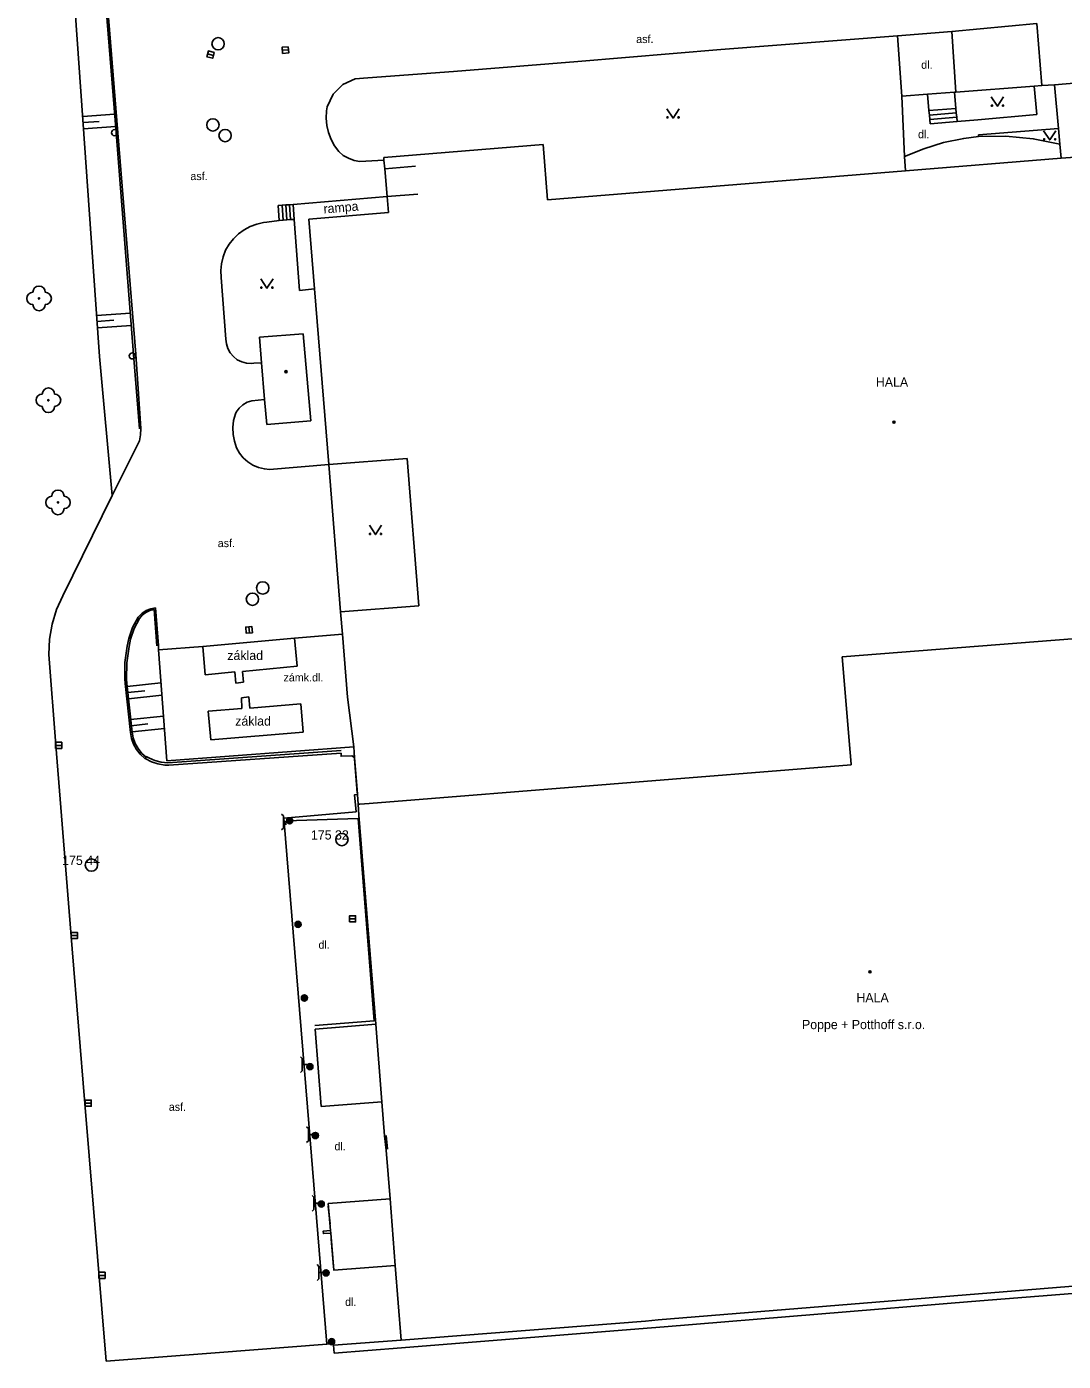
# Model space of a CAD drawing. Extents: x -541281 to -539153, y -1183881 to -1182141.
# Drawn here: x -539600.4 to -539516.2, y -1183333.1 to -1183224.7 of the extents above; entities that cross this region are included whole.
import ezdxf

# ---------------------------------------------------------------- set-up
doc = ezdxf.new("R2010")
doc.units = 0
for name, color, linetype in [('Vrstva 10', 7, 'Continuous'), ('Vrstva 11', 7, 'Continuous'), ('Vrstva 14', 7, 'Continuous'), ('Vrstva 15', 7, 'Continuous'), ('Vrstva 22', 7, 'Continuous'), ('Vrstva 25', 7, 'Continuous'), ('Vrstva 27', 7, 'Continuous'), ('Vrstva 28', 7, 'Continuous'), ('Vrstva 36', 7, 'Continuous'), ('Vrstva 39', 7, 'Continuous'), ('Vrstva 4', 7, 'Continuous'), ('Vrstva 40', 7, 'Continuous'), ('Vrstva 41', 7, 'Continuous'), ('Vrstva 5', 7, 'Continuous'), ('Vrstva 6', 7, 'Continuous')]:
    doc.layers.add(name, color=color, linetype=linetype)

msp = doc.modelspace()

# ---------------------------------------------------------------- linework, layer by layer
at = {"layer": 'Vrstva 10'}
for p, q in [((-539593, -1183233.35), (-539594.42, -1183215.51)), ((-539529.69, -1183225.47), (-539525.28, -1183225.11)), ((-539525.28, -1183225.11), (-539518.39, -1183224.47)), ((-539525.28, -1183225.11), (-539524.95, -1183230.04)), ((-539518.39, -1183224.47), (-539517.97, -1183229.5)), ((-539544.03, -1183226.57), (-539529.69, -1183225.47)), ((-539555.66, -1183227.54), (-539544.03, -1183226.57)), ((-539572.71, -1183228.87), (-539565.75, -1183228.37)), ((-539565.75, -1183228.37), (-539555.66, -1183227.54)), ((-539524.95, -1183230.04), (-539518.6, -1183229.55)), ((-539516.96, -1183229.43), (-539507.39, -1183228.66)), ((-539591.55, -1183251.33), (-539593, -1183233.35)), ((-539571.39, -1183235.55), (-539573.35, -1183235.67)), ((-539578.77, -1183239.16), (-539571.13, -1183238.5)), ((-539580.89, -1183240.6), (-539579.9, -1183240.46)), ((-539578.68, -1183240.37), (-539578.26, -1183246.15)), ((-539584.23, -1183250.09), (-539584.62, -1183245.1)), ((-539578.26, -1183246.15), (-539577.03, -1183246)), ((-539591.12, -1183257.35), (-539591.55, -1183251.33)), ((-539581.95, -1183252.06), (-539581.33, -1183252.01)), ((-539582.13, -1183255.1), (-539581.08, -1183255.01)), ((-539575.88, -1183260.29), (-539580.69, -1183260.68)), ((-539574.91, -1183272.25), (-539575.88, -1183260.29)), ((-539574.77, -1183274.06), (-539578.65, -1183274.38)), ((-539586.11, -1183275.06), (-539589.7, -1183275.32)), ((-539586.11, -1183275.06), (-539578.65, -1183274.38)), ((-539586.11, -1183275.06), (-539585.91, -1183277.35)), ((-539578.44, -1183276.67), (-539578.65, -1183274.38)), ((-539598.6, -1183275.72), (-539598.04, -1183283.07)), ((-539585.91, -1183277.35), (-539583.49, -1183277.13)), ((-539583.49, -1183277.13), (-539583.41, -1183278.03)), ((-539582.89, -1183277.08), (-539578.44, -1183276.67)), ((-539582.81, -1183277.96), (-539582.89, -1183277.08)), ((-539592.41, -1183278.07), (-539591.98, -1183282.05)), ((-539583.41, -1183278.03), (-539582.81, -1183277.96)), ((-539582.37, -1183279.14), (-539582.96, -1183279.23)), ((-539582.96, -1183279.23), (-539582.92, -1183280.11)), ((-539582.28, -1183280.07), (-539582.37, -1183279.14)), ((-539582.92, -1183280.11), (-539585.66, -1183280.32)), ((-539585.66, -1183280.32), (-539585.45, -1183282.63)), ((-539578.13, -1183279.71), (-539582.28, -1183280.07)), ((-539577.95, -1183282.03), (-539578.13, -1183279.71)), ((-539585.45, -1183282.63), (-539577.95, -1183282.03)), ((-539598.04, -1183283.07), (-539596.7, -1183299.63)), ((-539574.87, -1183283.72), (-539588.85, -1183284.71)), ((-539579.52, -1183289), (-539573.64, -1183288.5)), ((-539577.61, -1183312.47), (-539579.52, -1183289)), ((-539596.7, -1183299.63), (-539595.67, -1183312.18)), ((-539595.67, -1183312.18), (-539593.96, -1183333.12)), ((-539576.04, -1183331.72), (-539577.61, -1183312.47)), ((-539593.96, -1183333.12), (-539585.11, -1183332.43)), ((-539585.11, -1183332.43), (-539576.04, -1183331.72)), ((-539575.61, -1183331.7), (-539576.04, -1183331.72))]:
    msp.add_line(p, q, dxfattribs=at)
for points in [[(-539576, -1183231.22), (-539575.53, -1183230.21), (-539574.74, -1183229.42), (-539573.72, -1183228.96), (-539572.71, -1183228.87)], [(-539518.6, -1183229.55), (-539517.97, -1183229.5), (-539516.96, -1183229.43)], [(-539575.06, -1183234.87), (-539575.41, -1183234.39), (-539575.69, -1183233.87), (-539575.9, -1183233.32), (-539576.03, -1183232.74), (-539576.08, -1183232.15), (-539576.05, -1183231.56), (-539576, -1183231.22)], [(-539573.35, -1183235.67), (-539573.82, -1183235.58), (-539574.28, -1183235.41), (-539574.7, -1183235.17), (-539575.06, -1183234.87)], [(-539584.62, -1183245.1), (-539584.65, -1183244.53), (-539584.59, -1183243.97), (-539584.46, -1183243.41), (-539584.25, -1183242.88), (-539583.96, -1183242.39), (-539583.62, -1183241.94), (-539583.21, -1183241.54), (-539582.75, -1183241.21), (-539582.25, -1183240.94), (-539581.71, -1183240.75), (-539581.16, -1183240.63), (-539580.89, -1183240.6)], [(-539584.23, -1183250.09), (-539584.19, -1183250.49), (-539584.07, -1183250.87), (-539583.87, -1183251.22), (-539583.61, -1183251.52), (-539583.3, -1183251.77), (-539582.94, -1183251.95), (-539582.56, -1183252.05), (-539582.16, -1183252.08), (-539581.95, -1183252.06)], [(-539582.13, -1183255.1), (-539582.51, -1183255.23), (-539582.85, -1183255.44), (-539583.15, -1183255.71), (-539583.39, -1183256.03), (-539583.46, -1183256.16)], [(-539583.46, -1183256.16), (-539583.6, -1183256.71), (-539583.66, -1183257.27), (-539583.64, -1183257.84), (-539583.54, -1183258.39), (-539583.37, -1183258.92)], [(-539591.25, -1183258.37), (-539591.15, -1183257.86), (-539591.12, -1183257.35)], [(-539591.25, -1183258.37), (-539593.45, -1183262.81), (-539597.47, -1183270.94)], [(-539583.37, -1183258.92), (-539583.13, -1183259.35), (-539582.82, -1183259.73), (-539582.45, -1183260.06), (-539582.03, -1183260.33), (-539581.58, -1183260.52), (-539581.1, -1183260.64), (-539580.69, -1183260.68)], [(-539597.47, -1183270.94), (-539597.97, -1183272.07), (-539598.33, -1183273.26), (-539598.54, -1183274.48), (-539598.6, -1183275.72)], [(-539589.93, -1183271.92), (-539590.32, -1183271.99), (-539590.69, -1183272.13), (-539591.02, -1183272.35), (-539591.3, -1183272.63), (-539591.35, -1183272.69)], [(-539589.93, -1183271.92), (-539589.7, -1183274.99), (-539589.7, -1183275.32)], [(-539591.35, -1183272.69), (-539591.81, -1183273.52), (-539592.12, -1183274.42), (-539592.24, -1183275.04)], [(-539592.24, -1183275.04), (-539592.42, -1183276.36), (-539592.43, -1183277.7), (-539592.41, -1183278.07)], [(-539591.98, -1183282.05), (-539591.89, -1183282.53), (-539591.73, -1183283), (-539591.49, -1183283.43), (-539591.19, -1183283.81), (-539590.82, -1183284.15), (-539590.79, -1183284.17)], [(-539573.79, -1183284.08), (-539573.99, -1183283.94), (-539574.87, -1183283.97), (-539574.87, -1183283.72)], [(-539590.79, -1183284.17), (-539590.28, -1183284.42), (-539589.75, -1183284.59), (-539589.19, -1183284.69), (-539588.85, -1183284.71)], [(-539573.64, -1183288.5), (-539573.78, -1183287.1), (-539573.54, -1183287.08)]]:
    msp.add_lwpolyline(points, dxfattribs=at)
at = {"layer": 'Vrstva 11'}
for p, q in [((-539594.6, -1183215.37), (-539593.14, -1183233.31)), ((-539529.69, -1183225.47), (-539529.35, -1183230.37)), ((-539518.6, -1183229.55), (-539518.38, -1183231.86)), ((-539529.35, -1183230.37), (-539527.26, -1183230.21)), ((-539529.35, -1183230.37), (-539529.13, -1183235.27)), ((-539527.26, -1183230.21), (-539525.06, -1183230.04)), ((-539527.26, -1183230.21), (-539527.15, -1183231.54)), ((-539525.06, -1183230.04), (-539524.95, -1183230.04)), ((-539527.15, -1183231.54), (-539524.95, -1183231.37)), ((-539524.92, -1183231.73), (-539527.11, -1183231.9)), ((-539518.38, -1183231.86), (-539523.18, -1183232.28)), ((-539527.07, -1183232.25), (-539524.89, -1183232.07)), ((-539527.03, -1183232.6), (-539524.86, -1183232.42)), ((-539523.18, -1183232.28), (-539524.86, -1183232.42)), ((-539593.14, -1183233.31), (-539591.72, -1183251.34)), ((-539523.11, -1183233.51), (-539516.63, -1183232.99)), ((-539523.11, -1183233.65), (-539523.11, -1183233.51)), ((-539579.99, -1183239.24), (-539579.9, -1183240.46)), ((-539579.67, -1183239.22), (-539579.58, -1183240.44)), ((-539579.37, -1183239.2), (-539579.28, -1183240.41)), ((-539579.07, -1183239.18), (-539578.98, -1183240.39)), ((-539578.68, -1183240.37), (-539578.77, -1183239.16)), ((-539591.72, -1183251.34), (-539591.25, -1183257.37)), ((-539589.84, -1183275.02), (-539590.06, -1183272.06)), ((-539589.7, -1183275.32), (-539589.02, -1183284.36)), ((-539592.27, -1183278.07), (-539591.85, -1183282.02)), ((-539589.02, -1183284.36), (-539573.85, -1183283.2)), ((-539574.88, -1183283.52), (-539588.95, -1183284.51)), ((-539579.34, -1183289.23), (-539579.36, -1183289.54)), ((-539573.49, -1183289.04), (-539579.34, -1183289.23)), ((-539572.2, -1183305.46), (-539573.49, -1183289.04)), ((-539577.01, -1183305.84), (-539572.2, -1183305.46)), ((-539523.68, -1183328.27), (-539490.74, -1183325.59)), ((-539548.64, -1183330.31), (-539523.68, -1183328.27)), ((-539569.98, -1183332.02), (-539550.69, -1183330.49)), ((-539550.69, -1183330.49), (-539548.64, -1183330.31)), ((-539570, -1183331.41), (-539575.48, -1183331.81)), ((-539575.48, -1183331.81), (-539575.43, -1183332.47)), ((-539575.43, -1183332.47), (-539569.98, -1183332.02))]:
    msp.add_line(p, q, dxfattribs=at)
for points in [[(-539516.96, -1183229.43), (-539516.63, -1183232.99), (-539516.52, -1183234.26)], [(-539524.86, -1183232.42), (-539524.89, -1183232.07), (-539524.92, -1183231.73), (-539524.95, -1183231.37), (-539525.06, -1183230.04)], [(-539527.15, -1183231.54), (-539527.11, -1183231.9), (-539527.07, -1183232.25), (-539527.03, -1183232.6)], [(-539579.99, -1183239.24), (-539579.67, -1183239.22), (-539579.37, -1183239.2), (-539579.07, -1183239.18), (-539578.77, -1183239.16)], [(-539579.9, -1183240.46), (-539579.58, -1183240.44), (-539579.28, -1183240.41), (-539578.98, -1183240.39), (-539578.68, -1183240.37)], [(-539591.23, -1183272.78), (-539591.68, -1183273.6), (-539591.98, -1183274.48), (-539592.09, -1183275.06)], [(-539590.06, -1183272.06), (-539590.41, -1183272.15), (-539590.74, -1183272.31), (-539591.03, -1183272.53), (-539591.23, -1183272.78)], [(-539592.09, -1183275.06), (-539592.27, -1183276.38), (-539592.29, -1183277.71), (-539592.27, -1183278.07)], [(-539591.85, -1183282.02), (-539591.76, -1183282.49), (-539591.6, -1183282.95), (-539591.36, -1183283.36), (-539591.05, -1183283.74), (-539590.71, -1183284.04)], [(-539590.69, -1183284), (-539590.71, -1183284.04), (-539590.79, -1183284.17)], [(-539588.95, -1183284.51), (-539589.48, -1183284.45), (-539590, -1183284.32), (-539590.49, -1183284.11), (-539590.69, -1183284)]]:
    msp.add_lwpolyline(points, dxfattribs=at)
at = {"layer": 'Vrstva 14'}
for p, q in [((-539597.12, -1183214.51), (-539595.75, -1183233.41)), ((-539595.75, -1183233.41), (-539594.5, -1183251.51)), ((-539594.5, -1183251.51), (-539593.45, -1183262.81))]:
    msp.add_line(p, q, dxfattribs=at)
at = {"layer": 'Vrstva 15'}
for p, q in [((-539595.85, -1183232.01), (-539593.26, -1183231.82)), ((-539595.82, -1183232.51), (-539594.52, -1183232.42)), ((-539595.78, -1183233.01), (-539593.18, -1183232.82)), ((-539594.73, -1183248.17), (-539591.98, -1183247.98)), ((-539594.7, -1183248.67), (-539593.32, -1183248.57)), ((-539594.66, -1183249.17), (-539591.91, -1183248.98)), ((-539592.24, -1183278.31), (-539589.5, -1183278.02)), ((-539592.19, -1183278.81), (-539590.82, -1183278.67)), ((-539592.14, -1183279.31), (-539589.42, -1183279.02)), ((-539591.96, -1183281), (-539589.29, -1183280.72)), ((-539591.91, -1183281.5), (-539590.57, -1183281.35)), ((-539591.85, -1183281.99), (-539589.22, -1183281.71))]:
    msp.add_line(p, q, dxfattribs=at)
at = {"layer": 'Vrstva 22'}
for centre in [(-539599.4, -1183246.79), (-539598.64, -1183255.06), (-539597.86, -1183263.36)]:
    msp.add_circle(centre, 0.05, dxfattribs=at)
for centre, start, end in [((-539599.4, -1183246.29), 0, 180), ((-539599.9, -1183246.79), 90, 270), ((-539598.9, -1183246.79), 270, 90), ((-539599.4, -1183247.29), 180, 0), ((-539599.14, -1183255.06), 90, 270), ((-539598.64, -1183254.56), 0, 180), ((-539598.14, -1183255.06), 270, 90), ((-539598.64, -1183255.56), 180, 0), ((-539598.36, -1183263.36), 90, 270), ((-539597.86, -1183262.86), 0, 180), ((-539597.36, -1183263.36), 270, 90), ((-539597.86, -1183263.86), 180, 0)]:
    msp.add_arc(centre, 0.5, start, end, dxfattribs=at)
at = {"layer": 'Vrstva 25'}
for centre, radius in [((-539579.04, -1183289.22), 0.25), ((-539579.04, -1183289.22), 0.2), ((-539579.04, -1183289.22), 0.15), ((-539579.04, -1183289.22), 0.1), ((-539579.04, -1183289.22), 0.05), ((-539578.36, -1183297.63), 0.25), ((-539578.36, -1183297.63), 0.2), ((-539578.36, -1183297.63), 0.15), ((-539578.36, -1183297.63), 0.1), ((-539578.36, -1183297.63), 0.05), ((-539577.85, -1183303.61), 0.25), ((-539577.85, -1183303.61), 0.2), ((-539577.85, -1183303.61), 0.15), ((-539577.85, -1183303.61), 0.1), ((-539577.85, -1183303.61), 0.05), ((-539577.41, -1183309.19), 0.25), ((-539577.41, -1183309.19), 0.2), ((-539577.41, -1183309.19), 0.15), ((-539577.41, -1183309.19), 0.1), ((-539577.41, -1183309.19), 0.05), ((-539576.96, -1183314.78), 0.25), ((-539576.96, -1183314.78), 0.2), ((-539576.96, -1183314.78), 0.15), ((-539576.96, -1183314.78), 0.1), ((-539576.96, -1183314.78), 0.05), ((-539576.49, -1183320.35), 0.25), ((-539576.49, -1183320.35), 0.2), ((-539576.49, -1183320.35), 0.15), ((-539576.49, -1183320.35), 0.1), ((-539576.49, -1183320.35), 0.05), ((-539576.09, -1183325.94), 0.25), ((-539576.09, -1183325.94), 0.2), ((-539576.09, -1183325.94), 0.15), ((-539576.09, -1183325.94), 0.1), ((-539576.09, -1183325.94), 0.05), ((-539575.65, -1183331.53), 0.25), ((-539575.65, -1183331.53), 0.2), ((-539575.65, -1183331.53), 0.15), ((-539575.65, -1183331.53), 0.1), ((-539575.65, -1183331.53), 0.05)]:
    msp.add_circle(centre, radius, dxfattribs=at)
at = {"layer": 'Vrstva 27'}
for p, q in [((-539585.23, -1183227.05), (-539585.71, -1183226.93)), ((-539579.14, -1183226.6), (-539579.64, -1183226.64)), ((-539582.32, -1183273.96), (-539582.36, -1183273.46)), ((-539598.05, -1183283.09), (-539597.55, -1183283.09)), ((-539579.7, -1183288.67), (-539579.56, -1183288.81)), ((-539579.56, -1183289.81), (-539579.56, -1183288.81)), ((-539579.56, -1183289.31), (-539579.07, -1183289.31)), ((-539579.7, -1183289.95), (-539579.56, -1183289.81)), ((-539574.19, -1183297.18), (-539573.69, -1183297.18)), ((-539596.78, -1183298.54), (-539596.28, -1183298.54)), ((-539578.18, -1183308.38), (-539578.04, -1183308.52)), ((-539578.04, -1183309.52), (-539578.04, -1183308.52)), ((-539578.18, -1183309.66), (-539578.04, -1183309.52)), ((-539578.04, -1183309.02), (-539577.55, -1183309.02)), ((-539595.66, -1183312.15), (-539595.16, -1183312.15)), ((-539577.67, -1183314.07), (-539577.53, -1183314.21)), ((-539577.53, -1183315.21), (-539577.53, -1183314.21)), ((-539577.67, -1183315.35), (-539577.53, -1183315.21)), ((-539577.53, -1183314.71), (-539577.04, -1183314.71)), ((-539577.22, -1183319.64), (-539577.08, -1183319.78)), ((-539577.08, -1183320.78), (-539577.08, -1183319.78)), ((-539577.08, -1183320.28), (-539576.59, -1183320.28)), ((-539577.22, -1183320.92), (-539577.08, -1183320.78)), ((-539594.54, -1183326.14), (-539594.04, -1183326.14)), ((-539576.82, -1183325.27), (-539576.68, -1183325.41)), ((-539576.68, -1183326.41), (-539576.68, -1183325.41)), ((-539576.68, -1183325.91), (-539576.19, -1183325.91)), ((-539576.82, -1183326.55), (-539576.68, -1183326.41))]:
    msp.add_line(p, q, dxfattribs=at)
for points in [[(-539579.16, -1183226.35), (-539579.66, -1183226.39), (-539579.62, -1183226.89), (-539579.12, -1183226.85)], [(-539585.17, -1183226.81), (-539585.65, -1183226.69), (-539585.77, -1183227.17), (-539585.29, -1183227.29)], [(-539582.07, -1183273.94), (-539582.11, -1183273.44), (-539582.61, -1183273.48), (-539582.57, -1183273.98)], [(-539598.05, -1183283.34), (-539597.55, -1183283.34), (-539597.55, -1183282.84), (-539598.05, -1183282.84)], [(-539574.19, -1183297.43), (-539573.69, -1183297.43), (-539573.69, -1183296.93), (-539574.19, -1183296.93)], [(-539596.78, -1183298.79), (-539596.28, -1183298.79), (-539596.28, -1183298.29), (-539596.78, -1183298.29)], [(-539595.66, -1183312.4), (-539595.16, -1183312.4), (-539595.16, -1183311.9), (-539595.66, -1183311.9)], [(-539594.54, -1183326.39), (-539594.04, -1183326.39), (-539594.04, -1183325.89), (-539594.54, -1183325.89)]]:
    msp.add_lwpolyline(points, close=True, dxfattribs=at)
for centre in [(-539584.86, -1183226.11), (-539585.28, -1183232.7), (-539584.29, -1183233.56), (-539582.07, -1183271.22), (-539581.24, -1183270.31), (-539574.81, -1183290.74), (-539595.15, -1183292.81)]:
    msp.add_circle(centre, 0.5, dxfattribs=at)
at = {"layer": 'Vrstva 28'}
for centre in [(-539593.27, -1183233.33), (-539591.82, -1183251.46)]:
    msp.add_circle(centre, 0.25, dxfattribs=at)
at = {"layer": 'Vrstva 36'}
for points in [[(-539522.08, -1183230.43), (-539521.58, -1183231.18), (-539521.08, -1183230.43)], [(-539548.42, -1183231.39), (-539547.92, -1183232.14), (-539547.42, -1183231.39)], [(-539517.84, -1183233.17), (-539517.34, -1183233.92), (-539516.84, -1183233.17)], [(-539581.4, -1183245.21), (-539580.9, -1183245.96), (-539580.4, -1183245.21)], [(-539572.58, -1183265.22), (-539572.08, -1183265.97), (-539571.58, -1183265.22)]]:
    msp.add_lwpolyline(points, dxfattribs=at)
for centre in [(-539522.03, -1183231.13), (-539521.13, -1183231.13), (-539548.37, -1183232.09), (-539547.47, -1183232.09), (-539517.79, -1183233.87), (-539516.89, -1183233.87), (-539581.35, -1183245.91), (-539580.45, -1183245.91), (-539572.53, -1183265.92), (-539571.63, -1183265.92)]:
    msp.add_circle(centre, 0.05, dxfattribs=at)
at = {"layer": 'Vrstva 39'}
for centre, radius in [((-539579.35, -1183252.74), 0.09), ((-539579.35, -1183252.74), 0.0398), ((-539529.98, -1183256.84), 0.09), ((-539529.98, -1183256.84), 0.0398), ((-539531.93, -1183301.49), 0.09), ((-539531.93, -1183301.49), 0.0398)]:
    msp.add_circle(centre, radius, dxfattribs=at)
at = {"layer": 'Vrstva 5'}
for p, q in [((-539516.4, -1183235.41), (-539485.87, -1183232.95)), ((-539571.41, -1183235.35), (-539558.47, -1183234.3)), ((-539558.47, -1183234.3), (-539558.11, -1183238.77)), ((-539516.52, -1183234.26), (-539516.4, -1183235.41)), ((-539571.33, -1183236.26), (-539568.84, -1183236.05)), ((-539529.05, -1183236.43), (-539529.13, -1183235.27)), ((-539529.05, -1183236.43), (-539516.4, -1183235.41)), ((-539558.11, -1183238.77), (-539529.05, -1183236.43)), ((-539568.64, -1183238.31), (-539571.13, -1183238.5)), ((-539577.48, -1183240.36), (-539571.02, -1183239.81)), ((-539581.51, -1183249.93), (-539577.94, -1183249.68)), ((-539577.94, -1183249.68), (-539577.34, -1183256.73)), ((-539577.34, -1183256.73), (-539580.91, -1183257.03)), ((-539569.51, -1183259.79), (-539575.88, -1183260.29)), ((-539568.56, -1183271.75), (-539569.51, -1183259.79)), ((-539574.91, -1183272.25), (-539568.56, -1183271.75)), ((-539534.18, -1183275.9), (-539512.68, -1183274.23)), ((-539534.05, -1183277.51), (-539534.18, -1183275.9)), ((-539533.62, -1183282.73), (-539534.05, -1183277.51)), ((-539574.36, -1183279.18), (-539573.85, -1183283.2)), ((-539533.46, -1183284.63), (-539533.62, -1183282.73)), ((-539573.85, -1183283.2), (-539573.79, -1183284.08)), ((-539573.79, -1183284.08), (-539573.58, -1183286.67)), ((-539572.6, -1183287.81), (-539533.46, -1183284.67)), ((-539533.46, -1183284.67), (-539533.46, -1183284.63)), ((-539573.48, -1183287.88), (-539573.34, -1183287.87)), ((-539573.48, -1183287.88), (-539573.42, -1183288.77)), ((-539573.34, -1183287.87), (-539572.6, -1183287.81)), ((-539576.98, -1183306.14), (-539572.06, -1183305.75)), ((-539576.49, -1183312.42), (-539576.98, -1183306.14)), ((-539571.56, -1183312.05), (-539576.49, -1183312.42)), ((-539571.34, -1183314.81), (-539571.21, -1183315.96)), ((-539549.12, -1183329.76), (-539490.38, -1183324.99)), ((-539570, -1183331.41), (-539550.16, -1183329.85))]:
    msp.add_line(p, q, dxfattribs=at)
for points in [[(-539529.13, -1183235.27), (-539527.57, -1183234.63), (-539525.96, -1183234.13), (-539524.31, -1183233.79), (-539523.11, -1183233.65)], [(-539523.11, -1183233.65), (-539520.89, -1183233.62), (-539518.68, -1183233.82), (-539516.52, -1183234.26)], [(-539571.02, -1183239.81), (-539571.13, -1183238.5), (-539571.33, -1183236.26), (-539571.39, -1183235.55), (-539571.41, -1183235.35)], [(-539575.88, -1183260.29), (-539577.03, -1183246), (-539577.48, -1183240.36)], [(-539580.91, -1183257.03), (-539581.08, -1183255.01), (-539581.33, -1183252.01), (-539581.51, -1183249.93)], [(-539574.36, -1183279.18), (-539574.77, -1183274.06), (-539574.91, -1183272.25)], [(-539573.58, -1183286.67), (-539573.54, -1183287.08), (-539573.48, -1183287.88)], [(-539573.42, -1183288.77), (-539572.06, -1183305.75), (-539571.56, -1183312.05), (-539571.34, -1183314.81)], [(-539571.21, -1183315.96), (-539570.9, -1183319.92), (-539570.48, -1183325.33), (-539570, -1183331.41)], [(-539570.9, -1183319.92), (-539575.91, -1183320.31), (-539575.73, -1183322.5), (-539575.71, -1183322.7), (-539575.46, -1183325.72), (-539570.48, -1183325.33)], [(-539575.71, -1183322.7), (-539576.31, -1183322.75), (-539576.33, -1183322.55), (-539575.73, -1183322.5)]]:
    msp.add_lwpolyline(points, dxfattribs=at)
at = {"layer": 'Vrstva 6'}
for p, q in [((-539573.82, -1183283.85), (-539573.56, -1183286.96)), ((-539571.34, -1183314.81), (-539571.21, -1183315.96)), ((-539571.21, -1183314.78), (-539571.11, -1183315.89)), ((-539575.91, -1183320.53), (-539575.77, -1183321.96)), ((-539575.69, -1183323.19), (-539575.5, -1183325.42)), ((-539549.12, -1183329.76), (-539550.16, -1183329.85))]:
    msp.add_line(p, q, dxfattribs=at)

# ---------------------------------------------------------------- texts
at = {"layer": 'Vrstva 4'}
for s, p in [('175 32 ', (-539577.32, -1183290.74)), ('175 44 ', (-539597.52, -1183292.81))]:
    msp.add_text(s, height=0.75, dxfattribs=at).set_placement(p)
at = {"layer": 'Vrstva 40'}
for s, p in [('asf.', (-539550.91, -1183226.05)), ('dl.', (-539527.77, -1183228.14)), ('dl.', (-539528.03, -1183233.78)), ('asf.', (-539587.11, -1183237.18)), ('asf.', (-539584.89, -1183266.99)), ('zámk.dl.', (-539579.55, -1183277.9)), ('dl.', (-539576.71, -1183299.61)), ('asf.', (-539588.86, -1183312.78)), ('dl.', (-539575.41, -1183315.98)), ('dl.', (-539574.55, -1183328.62))]:
    msp.add_text(s, height=0.65, dxfattribs=at).set_placement(p)
at = {"layer": 'Vrstva 41'}
msp.add_text('rampa', height=0.75, rotation=5, dxfattribs=at).set_placement((-539576.27, -1183239.9))
for s, p in [('HALA', (-539531.45, -1183253.96)), ('základ', (-539584.11, -1183276.16)), ('základ', (-539583.47, -1183281.49)), ('HALA', (-539533.03, -1183303.96)), ('Poppe + Potthoff s.r.o.', (-539537.45, -1183306.14))]:
    msp.add_text(s, height=0.75, dxfattribs=at).set_placement(p)

doc.saveas('drawing.dxf')
